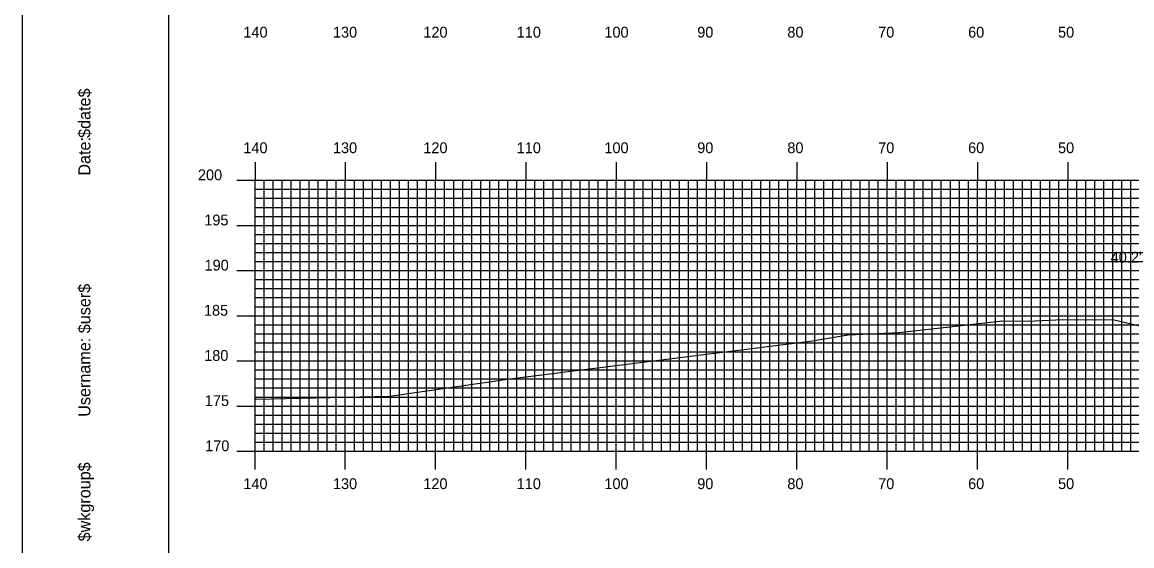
# Model space of a CAD drawing. Extents: x 1823966 to 1824309, y 442591 to 442811.
# Drawn here: x 1823966 to 1824088.9, y 442686.1 to 442744.1 of the extents above; entities that cross this region are included whole.
import ezdxf

# ---------------------------------------------------------------- set-up
doc = ezdxf.new("R2010")
doc.units = 0
for name, color, linetype in [('BORDER', 7, 'Continuous'), ('D_Text_Standard', 7, 'Continuous'), ('H_V ANNOTATION', 7, 'Continuous'), ('MAJOR', 7, 'Continuous'), ('MINOR', 7, 'Continuous'), ('PLOT BOUNDARY', 7, 'Continuous'), ('S_Roadway_Centerline', 7, 'Continuous')]:
    doc.layers.add(name, color=color, linetype=linetype)

msp = doc.modelspace()

# ---------------------------------------------------------------- linework, layer by layer
at = {"layer": 'BORDER'}
msp.add_lwpolyline([(1823982.22, 442596.67), (1824302.22, 442596.67), (1824302.22, 442806.67), (1823982.22, 442806.67)], close=True, dxfattribs=at)
at = {"layer": 'MAJOR'}
for p, q in [((1823991.82, 442728.59), (1823991.82, 442726.59)), ((1824001.82, 442728.59), (1824001.82, 442726.59)), ((1824011.82, 442728.59), (1824011.82, 442726.59)), ((1824021.82, 442728.59), (1824021.82, 442726.59)), ((1824031.82, 442728.59), (1824031.82, 442726.59)), ((1824041.82, 442728.59), (1824041.82, 442726.59)), ((1824051.82, 442728.59), (1824051.82, 442726.59)), ((1824061.82, 442728.59), (1824061.82, 442726.59)), ((1824071.82, 442728.59), (1824071.82, 442726.59)), ((1824081.82, 442728.59), (1824081.82, 442726.59)), ((1823989.82, 442726.59), (1823991.82, 442726.59)), ((1823991.82, 442726.59), (1824271.82, 442726.59)), ((1823991.82, 442696.59), (1823991.82, 442726.59)), ((1823991.82, 442696.59), (1823991.82, 442726.59)), ((1823991.82, 442726.59), (1824271.82, 442726.59)), ((1824001.82, 442696.59), (1824001.82, 442726.59)), ((1824011.82, 442696.59), (1824011.82, 442726.59)), ((1824021.82, 442696.59), (1824021.82, 442726.59)), ((1824031.82, 442696.59), (1824031.82, 442726.59)), ((1824041.82, 442696.59), (1824041.82, 442726.59)), ((1824051.82, 442696.59), (1824051.82, 442726.59)), ((1824061.82, 442696.59), (1824061.82, 442726.59)), ((1824071.82, 442696.59), (1824071.82, 442726.59)), ((1824081.82, 442696.59), (1824081.82, 442726.59)), ((1823989.82, 442721.59), (1823991.82, 442721.59)), ((1823991.82, 442721.59), (1824271.82, 442721.59)), ((1823989.82, 442716.59), (1823991.82, 442716.59)), ((1823991.82, 442716.59), (1824271.82, 442716.59)), ((1823989.82, 442711.59), (1823991.82, 442711.59)), ((1823991.82, 442711.59), (1824271.82, 442711.59)), ((1823989.82, 442706.59), (1823991.82, 442706.59)), ((1823991.82, 442706.59), (1824271.82, 442706.59)), ((1823989.82, 442701.59), (1823991.82, 442701.59)), ((1823991.82, 442701.59), (1824271.82, 442701.59)), ((1823989.82, 442696.59), (1823991.82, 442696.59)), ((1823991.82, 442696.59), (1824271.82, 442696.59)), ((1823991.82, 442696.59), (1824271.82, 442696.59)), ((1823991.82, 442694.58), (1823991.82, 442696.59)), ((1824001.82, 442694.58), (1824001.82, 442696.59)), ((1824011.82, 442694.58), (1824011.82, 442696.59)), ((1824021.82, 442694.58), (1824021.82, 442696.59)), ((1824031.82, 442694.58), (1824031.82, 442696.59)), ((1824041.82, 442694.58), (1824041.82, 442696.59)), ((1824051.82, 442694.58), (1824051.82, 442696.59)), ((1824061.82, 442694.58), (1824061.82, 442696.59)), ((1824071.82, 442694.58), (1824071.82, 442696.59)), ((1824081.82, 442694.58), (1824081.82, 442696.59))]:
    msp.add_line(p, q, dxfattribs=at)
at = {"layer": 'MINOR'}
for p, q in [((1823991.82, 442725.59), (1824271.82, 442725.59)), ((1823991.82, 442725.59), (1823993.83, 442725.59)), ((1823992.82, 442696.59), (1823992.82, 442726.59)), ((1823993.82, 442696.59), (1823993.82, 442726.59)), ((1823994.82, 442696.59), (1823994.82, 442726.59)), ((1823995.82, 442696.59), (1823995.82, 442726.59)), ((1823996.82, 442696.59), (1823996.82, 442726.59)), ((1823997.82, 442696.59), (1823997.82, 442726.59)), ((1823998.82, 442696.59), (1823998.82, 442726.59)), ((1823999.82, 442696.59), (1823999.82, 442726.59)), ((1824000.82, 442696.59), (1824000.82, 442726.59)), ((1824002.82, 442696.59), (1824002.82, 442726.59)), ((1824003.82, 442696.59), (1824003.82, 442726.59)), ((1824004.82, 442696.59), (1824004.82, 442726.59)), ((1824005.82, 442696.59), (1824005.82, 442726.59)), ((1824006.82, 442696.59), (1824006.82, 442726.59)), ((1824007.82, 442696.59), (1824007.82, 442726.59)), ((1824008.82, 442696.59), (1824008.82, 442726.59)), ((1824009.82, 442696.59), (1824009.82, 442726.59)), ((1824010.82, 442696.59), (1824010.82, 442726.59)), ((1824012.82, 442696.59), (1824012.82, 442726.59)), ((1824013.82, 442696.59), (1824013.82, 442726.59)), ((1824014.82, 442696.59), (1824014.82, 442726.59)), ((1824015.82, 442696.59), (1824015.82, 442726.59)), ((1824016.82, 442696.59), (1824016.82, 442726.59)), ((1824017.82, 442696.59), (1824017.82, 442726.59)), ((1824018.82, 442696.59), (1824018.82, 442726.59)), ((1824019.82, 442696.59), (1824019.82, 442726.59)), ((1824020.82, 442696.59), (1824020.82, 442726.59)), ((1824022.82, 442696.59), (1824022.82, 442726.59)), ((1824023.82, 442696.59), (1824023.82, 442726.59)), ((1824024.82, 442696.59), (1824024.82, 442726.59)), ((1824025.82, 442696.59), (1824025.82, 442726.59)), ((1824026.82, 442696.59), (1824026.82, 442726.59)), ((1824027.82, 442696.59), (1824027.82, 442726.59)), ((1824028.82, 442696.59), (1824028.82, 442726.59)), ((1824029.82, 442696.59), (1824029.82, 442726.59)), ((1824030.82, 442696.59), (1824030.82, 442726.59)), ((1824032.82, 442696.59), (1824032.82, 442726.59)), ((1824033.82, 442696.59), (1824033.82, 442726.59)), ((1824034.82, 442696.59), (1824034.82, 442726.59)), ((1824035.82, 442696.59), (1824035.82, 442726.59)), ((1824036.82, 442696.59), (1824036.82, 442726.59)), ((1824037.82, 442696.59), (1824037.82, 442726.59)), ((1824038.82, 442696.59), (1824038.82, 442726.59)), ((1824039.82, 442696.59), (1824039.82, 442726.59)), ((1824040.82, 442696.59), (1824040.82, 442726.59)), ((1824042.82, 442696.59), (1824042.82, 442726.59)), ((1824043.82, 442696.59), (1824043.82, 442726.59)), ((1824044.82, 442696.59), (1824044.82, 442726.59)), ((1824045.82, 442696.59), (1824045.82, 442726.59)), ((1824046.82, 442696.59), (1824046.82, 442726.59)), ((1824047.82, 442696.59), (1824047.82, 442726.59)), ((1824048.82, 442696.59), (1824048.82, 442726.59)), ((1824049.82, 442696.59), (1824049.82, 442726.59)), ((1824050.82, 442696.59), (1824050.82, 442726.59)), ((1824052.82, 442696.59), (1824052.82, 442726.59)), ((1824053.82, 442696.59), (1824053.82, 442726.59)), ((1824054.82, 442696.59), (1824054.82, 442726.59)), ((1824055.82, 442696.59), (1824055.82, 442726.59)), ((1824056.82, 442696.59), (1824056.82, 442726.59)), ((1824057.82, 442696.59), (1824057.82, 442726.59)), ((1824058.82, 442696.59), (1824058.82, 442726.59)), ((1824059.82, 442696.59), (1824059.82, 442726.59)), ((1824060.82, 442696.59), (1824060.82, 442726.59)), ((1824062.82, 442696.59), (1824062.82, 442726.59)), ((1824063.82, 442696.59), (1824063.82, 442726.59)), ((1824064.82, 442696.59), (1824064.82, 442726.59)), ((1824065.82, 442696.59), (1824065.82, 442726.59)), ((1824066.82, 442696.59), (1824066.82, 442726.59)), ((1824067.82, 442696.59), (1824067.82, 442726.59)), ((1824068.82, 442696.59), (1824068.82, 442726.59)), ((1824069.82, 442696.59), (1824069.82, 442726.59)), ((1824070.82, 442696.59), (1824070.82, 442726.59)), ((1824072.82, 442696.59), (1824072.82, 442726.59)), ((1824073.82, 442696.59), (1824073.82, 442726.59)), ((1824074.82, 442696.59), (1824074.82, 442726.59)), ((1824075.82, 442696.59), (1824075.82, 442726.59)), ((1824076.82, 442696.59), (1824076.82, 442726.59)), ((1824077.82, 442696.59), (1824077.82, 442726.59)), ((1824078.82, 442696.59), (1824078.82, 442726.59)), ((1824079.82, 442696.59), (1824079.82, 442726.59)), ((1824080.82, 442696.59), (1824080.82, 442726.59)), ((1824082.82, 442696.59), (1824082.82, 442726.59)), ((1824083.82, 442696.59), (1824083.82, 442726.59)), ((1824084.82, 442696.59), (1824084.82, 442726.59)), ((1824085.82, 442696.59), (1824085.82, 442726.59)), ((1824086.82, 442696.59), (1824086.82, 442726.59)), ((1824087.82, 442696.59), (1824087.82, 442726.59)), ((1824088.82, 442696.59), (1824088.82, 442726.59)), ((1823991.82, 442724.59), (1824271.82, 442724.59)), ((1823991.82, 442723.59), (1824271.82, 442723.59)), ((1823991.82, 442723.59), (1823993.83, 442723.59)), ((1823991.82, 442722.59), (1824271.82, 442722.59)), ((1823991.82, 442722.59), (1823993.83, 442722.59)), ((1823991.82, 442720.59), (1824271.82, 442720.59)), ((1823991.82, 442720.59), (1823993.83, 442720.59)), ((1823991.82, 442719.59), (1824271.82, 442719.59)), ((1823991.82, 442719.59), (1823993.83, 442719.59)), ((1823991.82, 442718.59), (1824271.82, 442718.59)), ((1823991.82, 442718.59), (1823993.83, 442718.59)), ((1823991.82, 442717.59), (1824271.82, 442717.59)), ((1823991.82, 442717.59), (1823993.83, 442717.59)), ((1823991.82, 442715.59), (1824271.82, 442715.59)), ((1823991.82, 442715.59), (1823993.83, 442715.59)), ((1823991.82, 442714.59), (1824271.82, 442714.59)), ((1823991.82, 442714.59), (1823993.83, 442714.59)), ((1823991.82, 442713.59), (1824271.82, 442713.59)), ((1823991.82, 442713.59), (1823993.83, 442713.59)), ((1823991.82, 442712.59), (1824271.82, 442712.59)), ((1823991.82, 442712.59), (1823993.83, 442712.59)), ((1823991.82, 442710.59), (1824271.82, 442710.59)), ((1823991.82, 442710.59), (1823993.83, 442710.59)), ((1823991.82, 442709.59), (1824271.82, 442709.59)), ((1823991.82, 442709.59), (1823993.83, 442709.59)), ((1823991.82, 442708.59), (1824271.82, 442708.59)), ((1823991.82, 442708.59), (1823993.83, 442708.59)), ((1823991.82, 442707.59), (1824271.82, 442707.59)), ((1823991.82, 442707.59), (1823993.83, 442707.59)), ((1823991.82, 442705.59), (1824271.82, 442705.59)), ((1823991.82, 442705.59), (1823993.83, 442705.59)), ((1823991.82, 442704.59), (1824271.82, 442704.59)), ((1823991.82, 442704.59), (1823993.83, 442704.59)), ((1823991.82, 442703.59), (1824271.82, 442703.59)), ((1823991.82, 442703.59), (1823993.83, 442703.59)), ((1823991.82, 442702.59), (1824271.82, 442702.59)), ((1823991.82, 442702.59), (1823993.83, 442702.59)), ((1823991.82, 442700.59), (1824271.82, 442700.59)), ((1823991.82, 442700.59), (1823993.83, 442700.59)), ((1823991.82, 442699.59), (1824271.82, 442699.59)), ((1823991.82, 442699.59), (1823993.83, 442699.59)), ((1823991.82, 442698.59), (1824271.82, 442698.59)), ((1823991.82, 442698.59), (1823993.83, 442698.59)), ((1823991.82, 442697.59), (1824271.82, 442697.59)), ((1823991.82, 442697.59), (1823993.83, 442697.59))]:
    msp.add_line(p, q, dxfattribs=at)
at = {"layer": 'PLOT BOUNDARY'}
msp.add_lwpolyline([(1823966.04, 442590.55), (1824306.04, 442590.55), (1824306.04, 442810.55), (1823966.04, 442810.55)], close=True, dxfattribs=at)
at = {"layer": 'S_Roadway_Centerline'}
msp.add_lwpolyline([(1823991.82, 442702.34), (1823991.96, 442702.34), (1824006.74, 442702.7), (1824020.04, 442704.59), (1824053.3, 442708.76), (1824057.52, 442709.47), (1824063.14, 442709.75), (1824074.6, 442711.03), (1824077.45, 442710.99), (1824081.27, 442711.16), (1824086.96, 442711.12), (1824091.67, 442710.03)], dxfattribs=at)

# ---------------------------------------------------------------- texts
at = {"layer": 'BORDER'}
for s, p in [('$date$', (1823973.59, 442731.28)), ('Date:', (1823973.59, 442727.1)), ('$user$', (1823973.59, 442709.65)), ('Username:', (1823973.59, 442700.4)), ('$wkgroup$', (1823973.59, 442686.6))]:
    msp.add_text(s, height=1.339, rotation=90, dxfattribs=at).set_placement(p)
at = {"layer": 'D_Text_Standard'}
msp.add_text("40.2'", height=1.2, dxfattribs=at).set_placement((1824086.58, 442717.47))
at = {"layer": 'H_V ANNOTATION'}
for s, p in [('140', (1823990.53, 442742.39)), ('130', (1824000.45, 442742.39)), ('120', (1824010.46, 442742.39)), ('110', (1824020.8, 442742.39)), ('100', (1824030.51, 442742.39)), ('90', (1824040.79, 442742.39)), ('80', (1824050.77, 442742.39)), ('70', (1824060.83, 442742.39)), ('60', (1824070.79, 442742.39)), ('50', (1824080.75, 442742.39)), ('140', (1823990.53, 442729.59)), ('130', (1824000.45, 442729.59)), ('120', (1824010.46, 442729.59)), ('110', (1824020.8, 442729.59)), ('100', (1824030.51, 442729.59)), ('90', (1824040.79, 442729.59)), ('80', (1824050.77, 442729.59)), ('70', (1824060.83, 442729.59)), ('60', (1824070.79, 442729.59)), ('50', (1824080.75, 442729.59)), ('200', (1823985.5, 442726.59)), ('195', (1823986.2, 442721.59)), ('190', (1823986.23, 442716.59)), ('185', (1823986.16, 442711.59)), ('180', (1823986.19, 442706.59)), ('175', (1823986.26, 442701.59)), ('170', (1823986.3, 442696.59)), ('140', (1823990.53, 442692.39)), ('130', (1824000.45, 442692.39)), ('120', (1824010.46, 442692.39)), ('110', (1824020.8, 442692.39)), ('100', (1824030.51, 442692.39)), ('90', (1824040.79, 442692.39)), ('80', (1824050.77, 442692.39)), ('70', (1824060.83, 442692.39)), ('60', (1824070.79, 442692.39)), ('50', (1824080.75, 442692.39))]:
    msp.add_text(s, height=1.2, dxfattribs=at).set_placement(p)
at = {"layer": 'MAJOR'}
msp.add_text('-', height=0.012, dxfattribs=at).set_placement((1823991.81, 442696.59))

doc.saveas('drawing.dxf')
